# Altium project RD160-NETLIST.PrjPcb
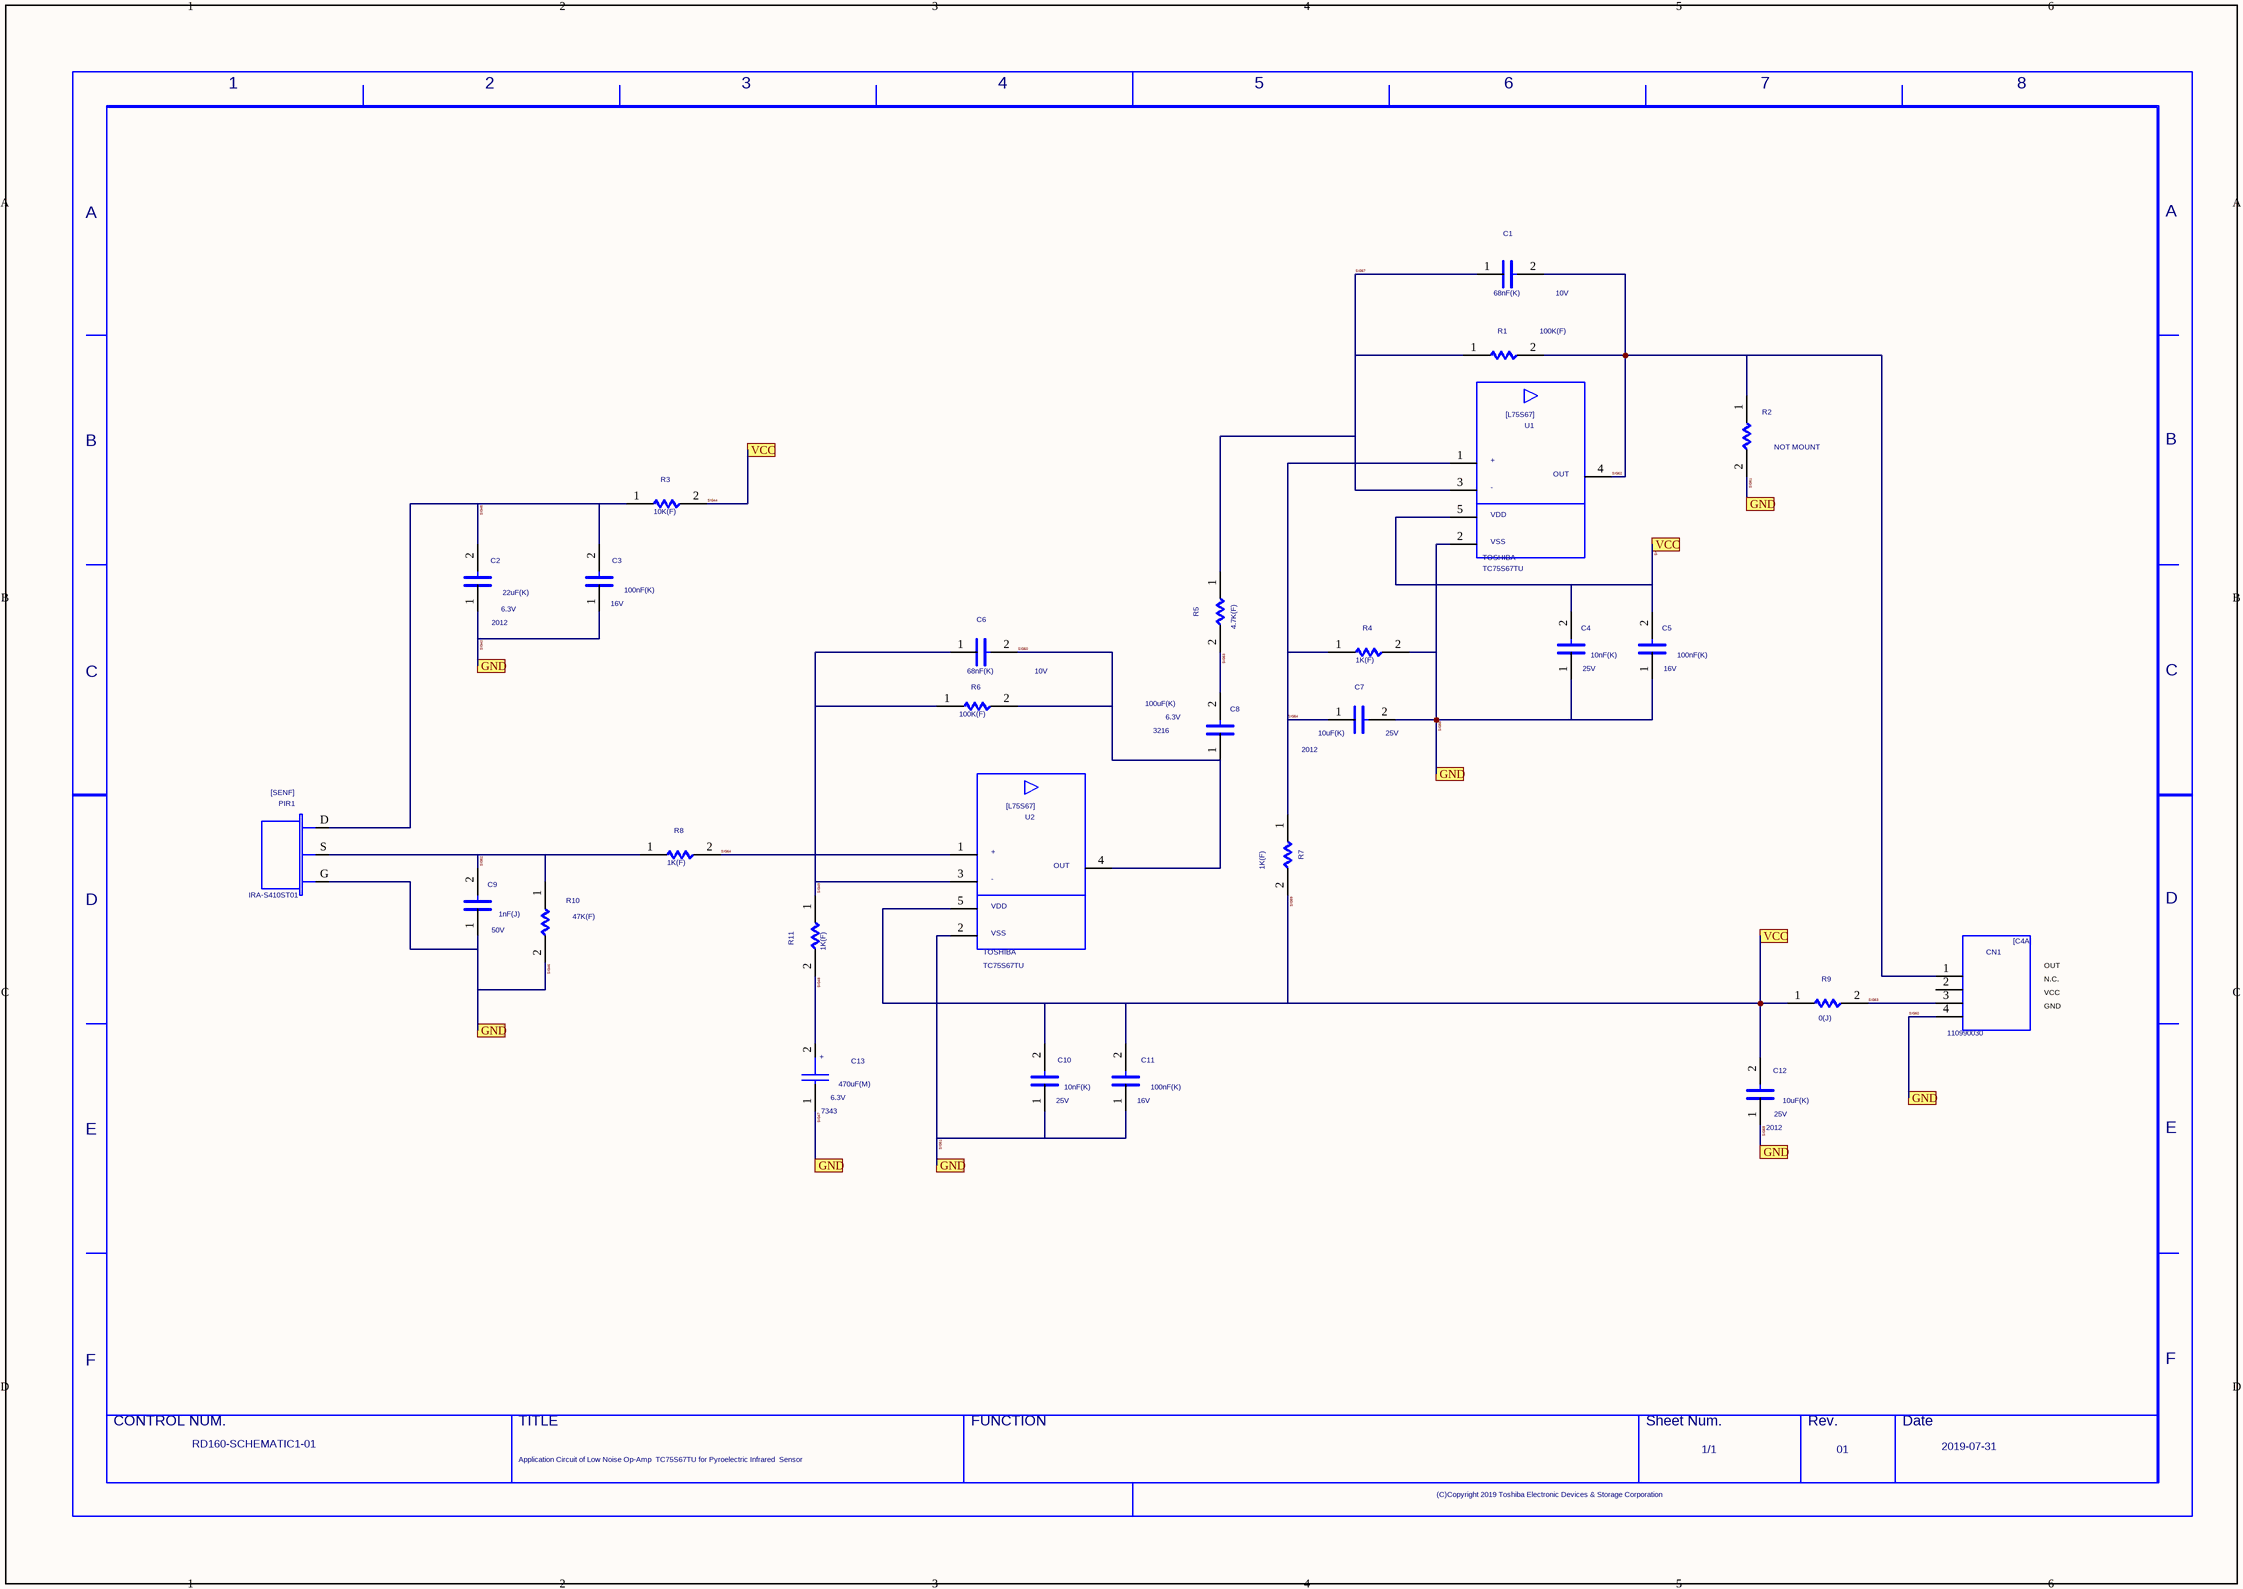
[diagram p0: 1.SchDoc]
1 sheet, 29 parts. Net scope: flat (ports and power ports of the same name join across sheets).

## Sheet 1.SchDoc
size 420 x 297 mm

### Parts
C1  VAL2: 10V  VAL1: 68nF(K)  (hidden comment: C)
C2  SIZECODESMD: 2012  VAL2: 6.3V  VAL1: 22uF(K)  (hidden comment: C)
C3  VAL2: 16V  VAL1: 100nF(K)  (hidden comment: C)
C4  VAL2: 25V  VAL1: 10nF(K)  (hidden comment: C)
C5  VAL2: 16V  VAL1: 100nF(K)  (hidden comment: C)
C6  VAL2: 10V  VAL1: 68nF(K)  (hidden comment: C)
C7  SIZECODESMD: 2012  VAL2: 25V  VAL1: 10uF(K)  (hidden comment: C)
C8  SIZECODESMD: 3216  VAL2: 6.3V  VAL1: 100uF(K)  (hidden comment: C)
C9  VAL2: 50V  VAL1: 1nF(J)  (hidden comment: C)
C10  VAL2: 25V  VAL1: 10nF(K)  (hidden comment: C)
C11  VAL2: 16V  VAL1: 100nF(K)  (hidden comment: C)
C12  SIZECODESMD: 2012  VAL2: 25V  VAL1: 10uF(K)  (hidden comment: C)
C13  SIZECODESMD: 7343  VAL2: 6.3V  VAL1: 470uF(M)  (hidden comment: CP)
CN1  VAL3: 110990030  (hidden comment: C4A)
PIR1  VAL3: IRA-S410ST01  (hidden comment: SENF)
R1  VAL1: 100K(F)  (hidden comment: R)
R2  NOTMOUNT: NOT MOUNT  (hidden comment: R)
R3  VAL1: 10K(F)  (hidden comment: R)
R4  VAL1: 1K(F)  (hidden comment: R)
R5  VAL1: 4.7K(F)  (hidden comment: R)
R6  VAL1: 100K(F)  (hidden comment: R)
R7  VAL1: 1K(F)  (hidden comment: R)
R8  VAL1: 1K(F)  (hidden comment: R)
R9  VAL1: 0(J)  (hidden comment: R)
R10  VAL1: 47K(F)  (hidden comment: R)
R11  VAL1: 1K(F)  (hidden comment: R)
U1  USERCOMPTEXT3: TOSHIBA  VAL3: TC75S67TU  (hidden comment: L75S67)
U2  USERCOMPTEXT3: TOSHIBA  VAL3: TC75S67TU  (hidden comment: L75S67)
U?  DATE: 2019-07-31  REVISION: 01  SHEETNUMBER: 1/1  TITLE: Application Circuit of Low Noise Op-Amp / TC75S67TU for Pyroelectric Infrared / Sensor  DRAWINGNUMBER: RD160-SCHEMATIC1-01  (hidden comment: WAKU_DEF100)

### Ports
GND, VCC

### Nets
SIG43: C2.1 C3.1 C4.1 C5.1 C7.2 C9.1 C10.1 C11.1 C12.1 C13.1 CN1.4 PIR1.G R2.2 R4.2 R10.2 U1.2 U2.2 ; port GND  [also labelled SIG46, SIG47, SIG51, SIG56, SIG58, SIG60, SIG61]
SIG44: C4.2 C5.2 C10.2 C11.2 C12.2 R3.2 R7.2 R9.1 U1.5 U2.5 ; port VCC  [also labelled SIG55, SIG59]
SIG45: C2.2 C3.2 PIR1.D R3.1
SIG48: C13.2 R11.2
SIG49: C6.1 R6.1 R11.1 U2.3
SIG50: C6.2 C8.1 R6.2 U2.4
SIG52: C9.2 PIR1.S R8.1 R10.1
SIG53: C8.2 R5.2
SIG54: C7.1 R4.1 R7.1 U1.1
SIG57: C1.1 R1.1 R5.1 U1.3
SIG62: C1.2 CN1.1 R1.2 R2.1 U1.4
SIG63: CN1.3 R9.2
SIG64: R8.2 U2.1

Not connected (* = marked no-connect by the designer): CN1 2

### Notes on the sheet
- OUT
- N.C.
- VCC
- GND

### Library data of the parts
C1 C6 = C: PARTNAME: GDM030000025; OriginalSymbolOrigin: (2540,7620); MAXGCOUNT: 1; COMPONENTNAME: GDM030000025_package; SIZECODESMD: 1005
C2 = C: PARTNAME: K0301764; OriginalSymbolOrigin: (2540,7620); COMPONENTNAME: K0301764_package; MAXGCOUNT: 1
C3 C5 C11 = C: PARTNAME: G36030133036; OriginalSymbolOrigin: (2540,7620); MAXGCOUNT: 1; COMPONENTNAME: G36030133036_package; SIZECODESMD: 1005
C4 = C: PARTNAME: GDM030001142; OriginalSymbolOrigin: (2540,7620); COMPONENTNAME: GDM030001142_package; MAXGCOUNT: 1; SIZECODESMD: 1005
C7 C12 = C: PARTNAME: GDM030002009; OriginalSymbolOrigin: (2540,7620); COMPONENTNAME: GDM030002009_package; MAXGCOUNT: 1
C8 = C: PARTNAME: GDM030002243; OriginalSymbolOrigin: (2540,7620); COMPONENTNAME: GDM030002243_package; MAXGCOUNT: 1
C9 = C: PARTNAME: G36030133142; OriginalSymbolOrigin: (2540,7620); COMPONENTNAME: G36030133142_package; MAXGCOUNT: 1; SIZECODESMD: 1005
C10 = C: PARTNAME: GAS030000012; OriginalSymbolOrigin: (2540,7620); COMPONENTNAME: GAS030000012_package; MAXGCOUNT: 1; SIZECODESMD: 1005
C13 = CP: PARTNAME: K0301781; OUMEPARTTYPE: C; SAVEAREA0: -1450,-153,20294,13055; SAVECOUNT: 52; TIME: 15:02:55; UPDATEUSER: fukuda-y; UPDATETIME: 16:13:42; OriginalSymbolOrigin: (2540,10160); COMPONENTNAME: K0301781_package; MAXGCOUNT: 1
CN1 = C4A: PARTNAME: K22S001P; OUMEPARTTYPE: CN; SAVEAREA0: -8845,-265,28754,23475; SAVECOUNT: 22; TIME: 13:28:28; UPDATEUSER: tomizawa-y; UPDATETIME: 15:03:27; OriginalSymbolOrigin: (2540,20320); COMPONENTNAME: K22S001P_package; MAXGCOUNT: 1
PIR1 = SENF: PARTNAME: K47S002C; OUMEPARTTYPE: MT; TIME: 14:34:58; UPDATEUSER: w90028dm; UPDATETIME: 13:22:07; SAVECOUNT: 25; SAVEAREA0: -45006,-15118,60589,37447; OriginalSymbolOrigin: (2540,17780); COMPONENTNAME: K47S002C_package; MAXGCOUNT: 1
R1 R6 = R: PARTNAME: G510110J8105; OriginalSymbolOrigin: (5080,5080); MAXGCOUNT: 1; COMPONENTNAME: G510110J8105_package; SIZECODESMD: 1005; VAL2: 100mW
R2 = R: PARTNAME: GDM010000374; OriginalSymbolOrigin: (5080,5080); MAXGCOUNT: 1; COMPONENTNAME: GDM010000374_package; SIZECODESMD: 1005
R3 = R: PARTNAME: GDM010004244; OriginalSymbolOrigin: (5080,5080); MAXGCOUNT: 1; COMPONENTNAME: GDM010004244_package; SIZECODESMD: 1005; VAL2: 100mW
R4 R7 R8 R11 = R: PARTNAME: GDM010001350; OriginalSymbolOrigin: (5080,5080); MAXGCOUNT: 1; COMPONENTNAME: GDM010001350_package; SIZECODESMD: 1005; VAL2: 100mW
R5 = R: PARTNAME: GDM010001348; OriginalSymbolOrigin: (5080,5080); MAXGCOUNT: 1; COMPONENTNAME: GDM010001348_package; SIZECODESMD: 1005; VAL2: 100mW
R9 = R: PARTNAME: GDM010000374; OriginalSymbolOrigin: (5080,5080); MAXGCOUNT: 1; COMPONENTNAME: GDM010000374_package; SIZECODESMD: 1005; VAL2: 1A
R10 = R: PARTNAME: G510110J0109; OriginalSymbolOrigin: (5080,5080); COMPONENTNAME: G510110J0109_package; MAXGCOUNT: 1; SIZECODESMD: 1005; VAL2: 100mW
U1 U2 = L75S67: PARTNAME: K47S002A; OUMEPARTTYPE: IC; TIME: 16:27:13; UPDATEUSER: 19990028; UPDATETIME: 13:02:06; SAVECOUNT: 13; SAVEAREA0: -72307,-25685,103712,61936; OriginalSymbolOrigin: (5080,35560); COMPONENTNAME: K47S002A_package; MAXGCOUNT: 1
U? = WAKU_DEF100: PLOTTIME: HH:MM; SAVEAREA0: 198008,-65938,436964,90161; TIME: 14:30:25; UPDATEUSER: cae; UPDATETIME: 16:54:21; SAVECOUNT: 4; OriginalSymbolOrigin: (10160,284480); FUNCTION: None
